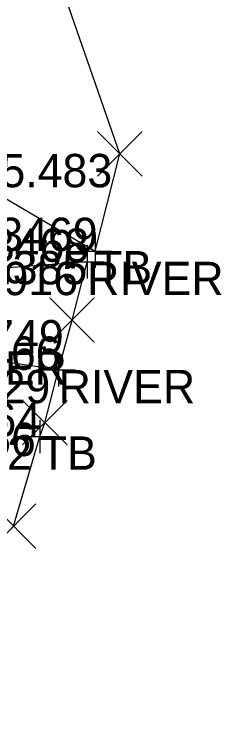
# Model space of a CAD drawing. Extents: x 2228183 to 2230895, y 679226 to 682223.
# Drawn here: x 2228398.61 to 2228404.81, y 680600.58 to 680622.17 of the extents above; entities that cross this region are included whole.
import ezdxf

# ---------------------------------------------------------------- set-up
doc = ezdxf.new("R2010")
doc.units = 0
for name, color, linetype in [('HY_X_Water_Edge', 7, 'Continuous'), ('SC_Scratch1', 7, 'Continuous'), ('SV_P_Control_Cells_Set', 7, 'Continuous'), ('SV_X_Random_Point', 7, 'Continuous'), ('SV_X_Shot_Marker', 7, 'Continuous'), ('SV_X_Terrain_Boundary', 7, 'Continuous'), ('SV_X_Text_Comment', 7, 'Continuous')]:
    doc.layers.add(name, color=color, linetype=linetype)

msp = doc.modelspace()

# ---------------------------------------------------------------- linework, layer by layer
at = {"layer": 'HY_X_Water_Edge'}
for points in [[(2228400.784, 680614.756), (2228394.338, 680614.261), (2228391.743, 680613.004), (2228389.936, 680611.52), (2228389.129, 680609.599), (2228389.139, 680607.547), (2228389.881, 680606.379), (2228389.158, 680602.955), (2228388.993, 680600.15)], [(2228399.931, 680611.516), (2228396.091, 680612.076), (2228393.265, 680610.862), (2228392.25, 680609.44), (2228392.081, 680607.538), (2228393.103, 680603.912), (2228394.443, 680597.985), (2228396.176, 680595.648), (2228396.942, 680593.007), (2228396.886, 680589.076), (2228395.848, 680586.101), (2228391.688, 680582.907), (2228389.707, 680579.835), (2228388.882, 680576.855), (2228387.084, 680574.698), (2228385.115, 680573.808), (2228383.229, 680572.475), (2228379.761, 680571.958), (2228376.722, 680571.582), (2228372.627, 680571.441), (2228369.35, 680573.216), (2228368.225, 680573.617), (2228367.397, 680575.9), (2228360.955, 680579.538)]]:
    msp.add_lwpolyline(points, dxfattribs=at)
at = {"layer": 'SV_X_Random_Point'}
for p, q in [((2228401.097, 680617.324), (2228402.431, 680618.659)), ((2228401.097, 680618.659), (2228402.431, 680617.324)), ((2228399.665, 680612.342), (2228400.999, 680613.677)), ((2228399.665, 680613.677), (2228400.999, 680612.342)), ((2228398.851, 680609.264), (2228400.185, 680610.599)), ((2228398.851, 680610.599), (2228400.185, 680609.264)), ((2228397.917, 680606.162), (2228399.251, 680607.497)), ((2228397.917, 680607.497), (2228399.251, 680606.162))]:
    msp.add_line(p, q, dxfattribs=at)
at = {"layer": 'SV_X_Shot_Marker'}
for p, q in [((2228401.022, 680615.579), (2228401.022, 680614.579)), ((2228400.522, 680615.079), (2228401.522, 680615.079)), ((2228400.784, 680615.256), (2228400.784, 680614.256)), ((2228401.022, 680615.079), (2228401.022, 680615.079)), ((2228400.284, 680614.756), (2228401.284, 680614.756)), ((2228400.784, 680614.756), (2228400.784, 680614.756)), ((2228399.931, 680612.016), (2228399.931, 680611.016)), ((2228399.431, 680611.516), (2228400.431, 680611.516)), ((2228399.931, 680611.516), (2228399.931, 680611.516)), ((2228399.367, 680610.021), (2228399.367, 680609.021)), ((2228398.867, 680609.521), (2228399.867, 680609.521)), ((2228399.367, 680609.521), (2228399.367, 680609.521))]:
    msp.add_line(p, q, dxfattribs=at)
at = {"layer": 'SV_X_Terrain_Boundary'}
msp.add_lwpolyline([(2228394.877, 680598.094), (2228394.349, 680601.809), (2228394.458, 680603.101), (2228395.551, 680603.732), (2228396.521, 680604.644), (2228398.584, 680606.829), (2228399.367, 680609.521), (2228399.518, 680609.931), (2228399.931, 680611.516), (2228400.332, 680613.009), (2228400.784, 680614.756), (2228394.338, 680614.261), (2228391.743, 680613.004), (2228391.856, 680613.495), (2228393.445, 680619.539), (2228401.022, 680615.079), (2228401.764, 680617.991), (2228396.833, 680632.175)], dxfattribs=at)

# ---------------------------------------------------------------- texts
at = {"layer": 'SC_Scratch1'}
for s, p in [('845.483', (2228396.7, 680616.991)), ('845.385', (2228395.952, 680614.079)), ('842.916', (2228395.68, 680613.756)), ('842.749', (2228395.248, 680612.009)), ('843.029', (2228394.847, 680610.516)), ('843.556', (2228394.414, 680608.931)), ('844.162', (2228394.294, 680608.521))]:
    msp.add_text(s, height=1, dxfattribs=at).set_placement(p)
at = {"layer": 'SV_P_Control_Cells_Set'}
for s, p in [('SV3469', (2228396.34, 680615.079)), ('SV3468', (2228396.085, 680614.756)), ('SV3466', (2228395.229, 680611.516)), ('SV3464', (2228394.647, 680609.521))]:
    msp.add_text(s, height=1, dxfattribs=at).set_placement(p)
at = {"layer": 'SV_X_Text_Comment'}
for s, p in [('TB', (2228401.022, 680614.079)), ('RIVER', (2228400.784, 680613.756)), ('RIVER', (2228396.091, 680611.076)), ('RIVER', (2228399.931, 680610.516)), ('TB', (2228399.367, 680608.521))]:
    msp.add_text(s, height=1, dxfattribs=at).set_placement(p)

doc.saveas('drawing.dxf')
